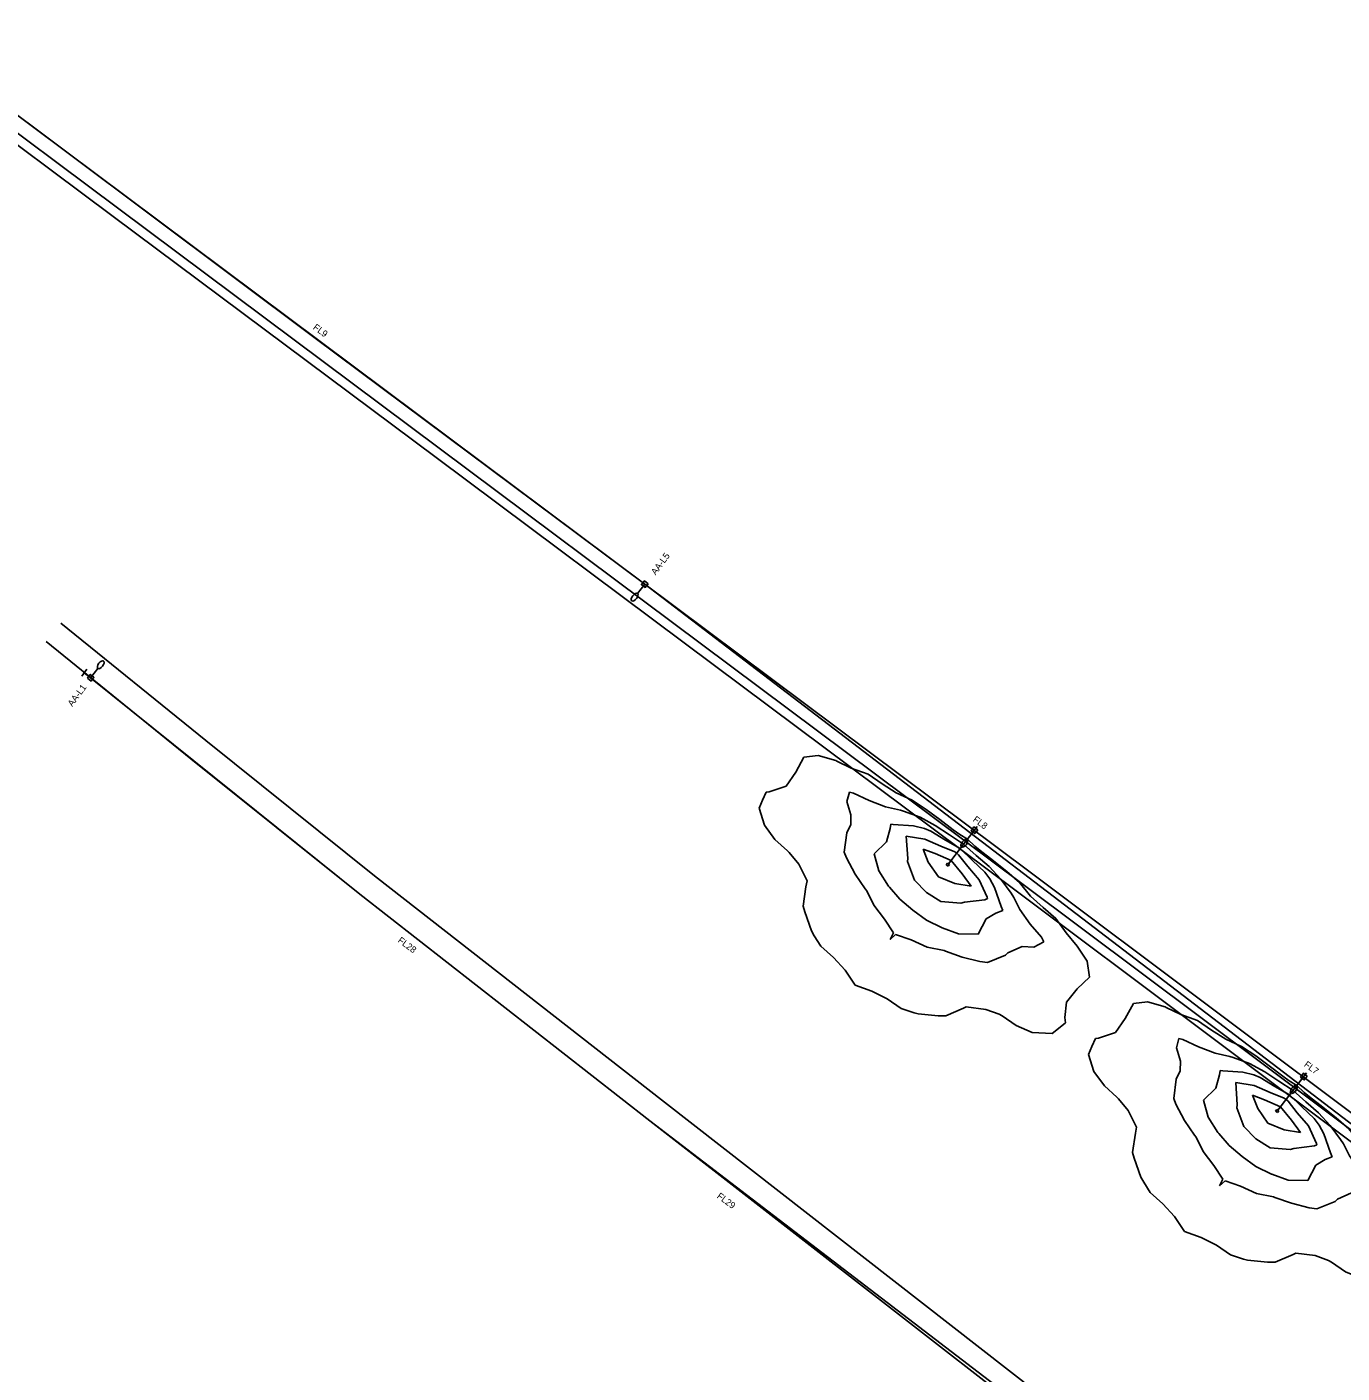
# Model space of a CAD drawing. Extents: x 1322666 to 1327584, y 458075 to 462260.
# Drawn here: x 1323755 to 1324314, y 460702 to 461275 of the extents above; entities that cross this region are included whole.
import ezdxf

# ---------------------------------------------------------------- set-up
doc = ezdxf.new("R2010")
doc.units = 0
for name, color, linetype in [('_CIVIL_CONSTRUCTION', 7, 'Continuous'), ('Default', 7, 'Continuous'), ('DR_P_Culvert', 7, 'Continuous'), ('DR_P_Culvert3D', 7, 'Continuous'), ('PF_X_Ground_Line', 7, 'Continuous'), ('UT_X_Misc_Cells', 7, 'Continuous'), ('UT_X_Oil', 7, 'Continuous')]:
    doc.layers.add(name, color=color, linetype=linetype)

# ---------------------------------------------------------------- blocks, each defined once
blk = doc.blocks.new('AGI32-IDj66arb-Project_1-LUMINAIRE-ERL2_19C330______Symbol')
at = {"layer": 'Default'}
for p, q in [((-0.03, 0), (0.03, 0)), ((0, 0.13), (0.24, 0.13)), ((0, -0.13), (0, 0.13)), ((0, 0.13), (0, 0.13)), ((0, 0.13), (0.24, 0.13)), ((0.24, 0.13), (0, 0.13)), ((0, -0.13), (0, 0.13)), ((0, 0.13), (0, 0.13)), ((0, 0.13), (0, -0.13)), ((0.24, 0.13), (0, 0.13)), ((0, 0.13), (0, -0.13)), ((0, -0.03), (0, 0.03)), ((0, 0.03), (0.03, 0)), ((0, -0.03), (0.03, 0)), ((0.24, 0.13), (0.24, -0.13)), ((0.24, 0.13), (0.24, 0.13)), ((0.24, 0.13), (0.24, 0.13)), ((0.24, 0.13), (0.24, -0.13)), ((0.24, -0.13), (0.24, 0.13)), ((0.24, -0.13), (0.24, 0.13)), ((0.24, -0.13), (0, -0.13)), ((0.24, -0.13), (0, -0.13)), ((0, -0.13), (0, -0.13)), ((0, -0.13), (0.24, -0.13)), ((0, -0.13), (0, -0.13)), ((0, -0.13), (0.24, -0.13)), ((0.24, -0.13), (0.24, -0.13)), ((0.24, -0.13), (0.24, -0.13))]:
    blk.add_line(p, q, dxfattribs=at)
blk = doc.blocks.new('AGI32-IDj66arb-Project_1-LUMINAIRE-ERL2_19C330______64-1')
at = {"layer": 'Default'}
blk.add_blockref('AGI32-IDj66arb-Project_1-LUMINAIRE-ERL2_19C330______Symbol', (0, 0), dxfattribs=at)
blk = doc.blocks.new('AGI32-IDj66arb-Project_1-LUMINAIRE-ERL2_19C330______Template1')
at = {"layer": 'Default'}
for p, q in [((10.58, 20.11), (10.97, 20.5)), ((10.97, 20.5), (12.6, 20.11)), ((4.29, 18.29), (5.49, 19.56)), ((5.49, 19.56), (7.31, 19.28)), ((7.31, 19.28), (9.14, 19.22)), ((9.14, 19.22), (10.58, 20.11)), ((12.6, 20.11), (12.8, 20.07)), ((12.8, 20.07), (13.99, 18.29)), ((3.66, 16.46), (4.29, 18.29)), ((13.99, 18.29), (14.48, 16.46)), ((3.25, 14.63), (3.66, 16.45)), ((3.66, 16.45), (3.66, 16.46)), ((14.48, 16.46), (14.57, 14.63)), ((2.69, 12.8), (3.25, 14.63)), ((14.57, 14.63), (14.63, 14.24)), ((5.23, 12.8), (5.49, 13.32)), ((5.49, 13.32), (6.62, 12.8)), ((14.63, 14.24), (15.08, 12.8)), ((2.59, 10.97), (2.69, 12.8)), ((4.85, 10.97), (5.23, 12.8)), ((6.62, 12.8), (7.31, 11.77)), ((7.31, 11.77), (8.8, 10.97)), ((15.08, 12.8), (16.17, 10.97)), ((2.44, 9.14), (2.59, 10.97)), ((4.29, 9.14), (4.85, 10.97)), ((8.8, 10.97), (9.14, 10.91)), ((9.14, 10.91), (10.97, 9.83)), ((16.17, 10.97), (16.46, 10.82)), ((16.46, 10.82), (18.29, 9.79)), ((2, 7.31), (2.44, 9.14)), ((3.66, 7.83), (4.29, 9.14)), ((10.97, 9.83), (11.39, 9.14)), ((11.39, 9.14), (12.17, 7.31)), ((18.29, 9.79), (18.8, 9.14)), ((18.8, 9.14), (19.94, 7.31)), ((1.89, 5.49), (2, 7.31)), ((2.95, 5.49), (3.47, 7.31)), ((3.47, 7.31), (3.66, 7.83)), ((4.09, 5.49), (5.27, 7.31)), ((5.27, 7.31), (5.49, 7.72)), ((5.49, 7.72), (6.19, 7.31)), ((6.19, 7.31), (7.31, 6.87)), ((12.17, 7.31), (12.76, 5.49)), ((19.94, 7.31), (20.11, 6.9)), ((7.31, 6.87), (9.14, 7.19)), ((9.14, 7.19), (10.42, 5.49)), ((20.11, 6.9), (20.59, 5.49)), ((1.86, 3.66), (1.89, 5.49)), ((2.64, 3.66), (2.95, 5.49)), ((3.42, 3.66), (3.66, 4.54)), ((3.66, 4.54), (4.09, 5.49)), ((4.43, 3.66), (5.39, 5.49)), ((5.39, 5.49), (5.49, 5.63)), ((5.49, 5.63), (5.75, 5.49)), ((5.75, 5.49), (7.31, 3.9)), ((10.42, 5.49), (10.97, 3.69)), ((12.76, 5.49), (12.8, 5.34)), ((12.8, 5.34), (13.64, 3.66)), ((20.59, 5.49), (20.69, 3.66)), ((1.85, 1.83), (1.86, 3.66)), ((2.53, 1.83), (2.64, 3.66)), ((3.22, 1.83), (3.42, 3.66)), ((4.03, 1.83), (4.43, 3.66)), ((5.05, 1.83), (5.49, 3.41)), ((5.49, 3.41), (6.36, 1.83)), ((7.31, 3.9), (7.65, 3.66)), ((7.65, 3.66), (8.83, 1.83)), ((10.97, 3.69), (10.98, 3.66)), ((10.98, 3.66), (11.36, 1.83)), ((13.64, 3.66), (14.06, 1.83)), ((20.69, 3.66), (21.05, 1.83)), ((1.83, 1.08), (1.85, 1.83)), ((2.41, 0), (2.53, 1.83)), ((3.01, 0), (3.22, 1.83)), ((3.66, 0.28), (4.03, 1.83)), ((4.62, 0), (5.05, 1.83)), ((6.36, 1.83), (6.85, 0)), ((8.83, 1.83), (8.98, 0)), ((11.36, 1.83), (11.4, 0)), ((14.06, 1.83), (14.63, 0.14)), ((21.05, 1.83), (21.63, 0)), ((1.73, 0), (1.83, 1.08)), ((3.62, 0), (3.66, 0.28)), ((14.63, 0.14), (15.4, 0)), ((1.83, -0.98), (1.73, 0)), ((1.85, -1.83), (1.83, -0.98)), ((2.55, -1.83), (2.41, 0)), ((3.25, -1.83), (3.01, 0)), ((3.66, -0.25), (3.62, 0)), ((4.07, -1.83), (3.66, -0.25)), ((5.07, -1.83), (4.62, 0)), ((6.85, 0), (6.29, -1.83)), ((8.98, 0), (8.72, -1.83)), ((11.4, 0), (11.31, -1.83)), ((14.63, -0.15), (14.04, -1.83)), ((15.4, 0), (14.63, -0.15)), ((21.63, 0), (20.99, -1.83)), ((1.88, -3.66), (1.85, -1.83)), ((2.67, -3.66), (2.55, -1.83)), ((3.47, -3.66), (3.25, -1.83)), ((4.53, -3.66), (4.07, -1.83)), ((5.49, -3.15), (5.07, -1.83)), ((6.29, -1.83), (5.49, -3.15)), ((8.72, -1.83), (7.6, -3.66)), ((11.31, -1.83), (10.97, -3.51)), ((14.04, -1.83), (13.56, -3.66)), ((20.99, -1.83), (20.7, -3.66)), ((1.89, -5.49), (1.88, -3.66)), ((2.97, -5.49), (2.67, -3.66)), ((3.66, -4.38), (3.47, -3.66)), ((5.49, -5.44), (4.53, -3.66)), ((7.31, -3.83), (5.49, -5.44)), ((7.6, -3.66), (7.31, -3.83)), ((10.94, -3.66), (10.29, -5.49)), ((10.97, -3.51), (10.94, -3.66)), ((13.56, -3.66), (12.8, -5.21)), ((20.7, -3.66), (20.55, -5.49)), ((2.03, -7.31), (1.89, -5.49)), ((3.54, -7.31), (2.97, -5.49)), ((4.15, -5.49), (3.66, -4.38)), ((5.37, -7.31), (4.15, -5.49)), ((10.29, -5.49), (9.14, -7.01)), ((12.73, -5.49), (12.12, -7.31)), ((12.8, -5.21), (12.73, -5.49)), ((20.55, -5.49), (20.11, -6.73)), ((7.31, -6.76), (5.91, -7.31)), ((9.14, -7.01), (7.31, -6.76)), ((20.11, -6.73), (19.86, -7.31)), ((2.46, -9.14), (2.03, -7.31)), ((3.66, -7.66), (3.54, -7.31)), ((4.35, -9.14), (3.66, -7.66)), ((5.49, -7.55), (5.37, -7.31)), ((5.91, -7.31), (5.49, -7.55)), ((12.12, -7.31), (11.3, -9.14)), ((19.86, -7.31), (18.68, -9.14)), ((2.61, -10.97), (2.46, -9.14)), ((4.89, -10.97), (4.35, -9.14)), ((10.97, -9.68), (9.14, -10.74)), ((11.3, -9.14), (10.97, -9.68)), ((18.29, -9.64), (16.46, -10.68)), ((18.68, -9.14), (18.29, -9.64)), ((2.71, -12.8), (2.61, -10.97)), ((5.29, -12.8), (4.89, -10.97)), ((7.31, -11.59), (6.44, -12.8)), ((8.15, -10.97), (7.31, -11.59)), ((9.14, -10.74), (8.15, -10.97)), ((15.87, -10.97), (14.99, -12.8)), ((16.46, -10.68), (15.87, -10.97)), ((3.3, -14.63), (2.71, -12.8)), ((5.49, -13.2), (5.29, -12.8)), ((6.44, -12.8), (5.49, -13.2)), ((14.99, -12.8), (14.63, -14.39)), ((14.63, -14.39), (14.6, -14.63)), ((3.66, -16.33), (3.3, -14.63)), ((14.6, -14.63), (14.44, -16.46)), ((3.68, -16.46), (3.66, -16.33)), ((4.41, -18.29), (3.68, -16.46)), ((14.44, -16.46), (13.9, -18.29)), ((5.49, -19.4), (4.41, -18.29)), ((13.9, -18.29), (12.8, -19.89)), ((7.31, -19.11), (5.49, -19.4)), ((9.14, -19.03), (7.31, -19.11)), ((10.75, -20.11), (9.14, -19.03)), ((10.97, -20.33), (10.75, -20.11)), ((11.9, -20.11), (10.97, -20.33)), ((12.8, -19.89), (11.9, -20.11))]:
    blk.add_line(p, q, dxfattribs=at)
blk = doc.blocks.new('AGI32-IDj66arb-Project_1-LUMINAIRE-ERL2_19C330______64')
at = {"layer": 'Default'}
for q in [(5.08, 0), (0, 0)]:
    blk.add_line((0, 0), q, dxfattribs=at)
for name, p in [('AGI32-IDj66arb-Project_1-LUMINAIRE-ERL2_19C330______Template1', (0, 0)), ('AGI32-IDj66arb-Project_1-LUMINAIRE-ERL2_19C330______64-1', (5.08, 0))]:
    blk.add_blockref(name, p, dxfattribs=at)

msp = doc.modelspace()

# ---------------------------------------------------------------- linework, layer by layer
at = {"layer": '_CIVIL_CONSTRUCTION'}
for p, q in [((1324017.44, 461037.65), (1324014.37, 461033.71)), ((1323781.75, 460997.82), (1323784.81, 461001.77))]:
    msp.add_line(p, q, dxfattribs=at)
for points in [[(1324018.85, 461037.82), (1324017.62, 461036.24), (1324016.04, 461037.47), (1324017.27, 461039.05)], [(1323780.35, 460997.64), (1323781.57, 460999.22), (1323783.15, 460998), (1323781.93, 460996.42)]]:
    msp.add_lwpolyline(points, close=True, dxfattribs=at)
for centre, major_axis in [((1324013.13, 461032.13), (-1.23, -1.58)), ((1323786.04, 461003.35), (1.23, 1.58))]:
    msp.add_ellipse(centre, major_axis=major_axis, ratio=0.5, dxfattribs=at)
at = {"layer": 'DR_P_Culvert'}
for p, q in [((1324157.66, 460932.91), (1324154.58, 460928.97)), ((1324297.78, 460828.1), (1324294.7, 460824.16))]:
    msp.add_line(p, q, dxfattribs=at)
for points in [[(1324159.06, 460933.09), (1324157.83, 460931.51), (1324156.25, 460932.74), (1324157.48, 460934.32)], [(1324299.18, 460828.27), (1324297.95, 460826.7), (1324296.38, 460827.93), (1324297.61, 460829.5)]]:
    msp.add_lwpolyline(points, close=True, dxfattribs=at)
for centre in [(1324153.35, 460927.4), (1324293.47, 460822.59)]:
    msp.add_ellipse(centre, major_axis=(-1.23, -1.58), ratio=0.5, dxfattribs=at)
at = {"layer": 'DR_P_Culvert3D'}
for points in [[(1325313.61, 460381.67), (1325288.02, 460385.96), (1325265.6, 460390.72), (1325174.92, 460418.01), (1325091.91, 460443.61), (1324989.4, 460474.51), (1324895.32, 460503.04), (1324830.48, 460523.41), (1324771.61, 460541.39), (1324709.26, 460561.9), (1324667.39, 460578.33), (1324617.11, 460602.1), (1324577.13, 460624.61), (1324508.29, 460671.66), (1324466.72, 460701.28), (1324334.23, 460800.54), (1324181.37, 460915.08), (1323797.37, 461202.12), (1323665.93, 461300.42), (1323464.99, 461451.01), (1323298.56, 461579.22)], [(1323292.45, 461571.3), (1323458.94, 461443.04), (1323659.93, 461292.42), (1323791.38, 461194.11), (1323928.66, 461091.5), (1324047.04, 461003.01), (1324175.38, 460907.08), (1324328.24, 460792.54), (1324460.82, 460693.21), (1324502.56, 460663.46), (1324571.84, 460616.11), (1324612.51, 460593.22), (1324663.42, 460569.15), (1324705.87, 460552.49), (1324768.59, 460531.86), (1324827.52, 460513.86), (1324892.37, 460493.49), (1324986.5, 460464.93), (1325088.99, 460434.04), (1325172, 460408.44), (1325263.12, 460381.03), (1325286.15, 460376.13), (1325311.95, 460371.8)], [(1325312.61, 460375.75), (1325286.9, 460380.06), (1325264.11, 460384.9), (1325173.17, 460412.27), (1325090.16, 460437.87), (1324987.66, 460468.76), (1324893.55, 460497.31), (1324828.71, 460517.68), (1324769.79, 460535.67), (1324707.22, 460556.25), (1324665.01, 460572.82), (1324614.35, 460596.77), (1324573.96, 460619.51), (1324504.85, 460666.74), (1324463.18, 460696.44), (1324330.63, 460795.74), (1324177.78, 460910.28), (1323793.78, 461197.32), (1323662.33, 461295.62), (1323461.36, 461446.23), (1323294.9, 461574.47)], [(1323769.14, 461021), (1323830.68, 460971.15), (1323902.43, 460913.55), (1324025.79, 460817.22), (1324184.37, 460693.72), (1324247.58, 460644), (1324302.39, 460600.37), (1324345.59, 460566.06), (1324422.31, 460505.74), (1324432.36, 460498.2), (1324443.79, 460488.66), (1324451.71, 460481.87), (1324470.52, 460465.4), (1324491.64, 460446.42), (1324531.14, 460408.67), (1324575.16, 460365.41), (1324616.32, 460324.05), (1324657.82, 460282.32), (1324698.81, 460237.16), (1324735.51, 460194.32)], [(1324727.92, 460187.81), (1324691.31, 460230.54), (1324650.57, 460275.43), (1324609.23, 460317), (1324568.11, 460358.31), (1324524.18, 460401.49), (1324484.84, 460439.09), (1324463.88, 460457.92), (1324445.16, 460474.31), (1324437.33, 460481.03), (1324426.16, 460490.36), (1324416.22, 460497.81), (1324339.39, 460558.21), (1324296.16, 460592.55), (1324241.37, 460636.16), (1324178.21, 460685.84), (1324019.64, 460809.33), (1323896.22, 460905.71), (1323824.4, 460963.36), (1323762.85, 461013.23)]]:
    msp.add_lwpolyline(points, dxfattribs=at)
at = {"layer": 'PF_X_Ground_Line'}
for points in [[(1324017.44, 461037.65), (1323877.23, 461142.38), (1323736.98, 461247.23)], [(1324410.85, 460736.87), (1324331.83, 460797.34), (1324017.44, 461037.65)], [(1324301.3, 460593.57), (1324019.64, 460809.33), (1323896.22, 460905.71), (1323781.75, 460997.82)]]:
    msp.add_lwpolyline(points, dxfattribs=at)
at = {"layer": 'UT_X_Oil'}
for p, q in [((1323780.13, 461001.45), (1323777.94, 460998.56)), ((1323782.18, 460997.51), (1323778.99, 460999.94))]:
    msp.add_line(p, q, dxfattribs=at)

# ---------------------------------------------------------------- block references
at = {"layer": 'DR_P_Culvert', "xscale": 3.9370000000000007, "yscale": 3.9370000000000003, "rotation": -127.5957929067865}
for p in [(1324158.84, 460934.51), (1324298.96, 460829.7)]:
    msp.add_blockref('AGI32-IDj66arb-Project_1-LUMINAIRE-ERL2_19C330______64', p, dxfattribs=at)

# ---------------------------------------------------------------- texts
at = {"layer": 'UT_X_Misc_Cells'}
for s, rotation, p in [('FL9', 323.4759, (1323876.08, 461146.38)), ('AA-L5', 53.4759, (1324022.08, 461041.33)), ('AA-L1', 53.4759, (1323773.96, 460985.33)), ('FL8', 323.4759, (1324156.76, 460936.99)), ('FL28', 323.4759, (1323912.14, 460885.53)), ('FL7', 323.4759, (1324297.59, 460832.69)), ('FL29', 323.4759, (1324047.87, 460776.71))]:
    msp.add_text(s, height=2.8, rotation=rotation, dxfattribs=at).set_placement(p)

doc.saveas('drawing.dxf')
